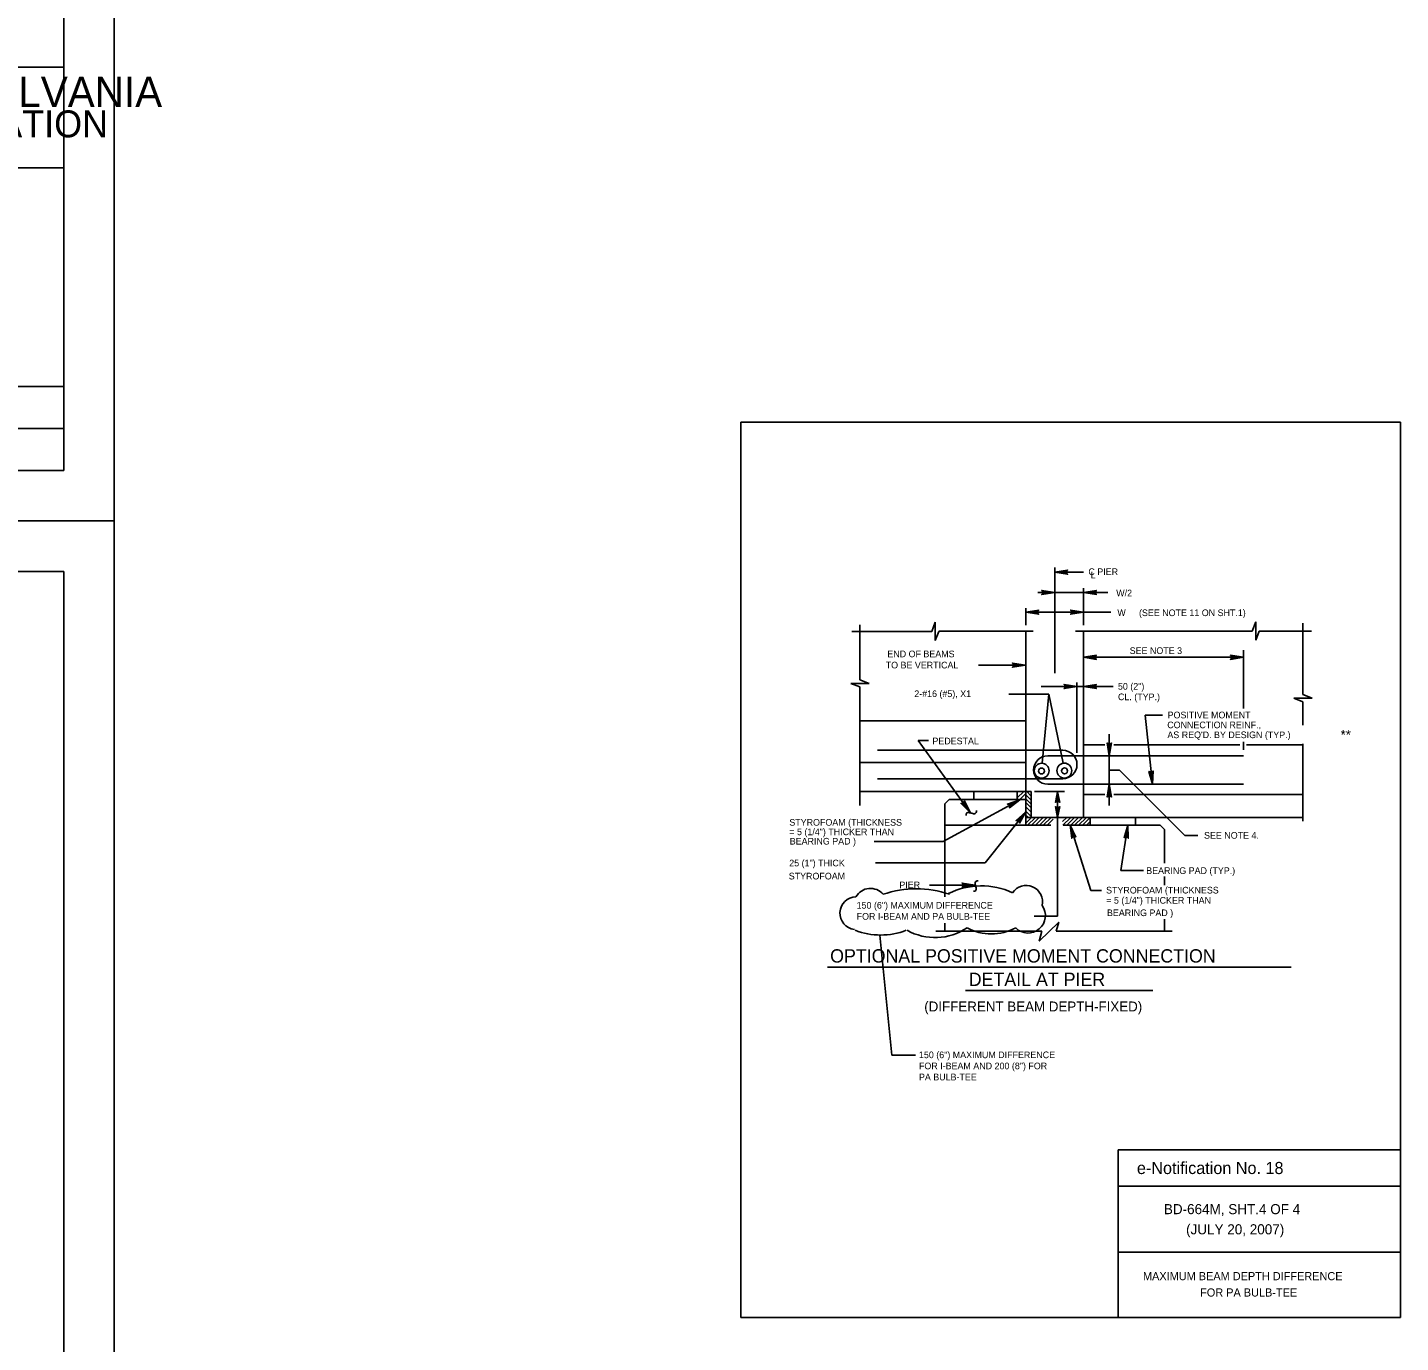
# Model space of a CAD drawing. Extents: x 639980 to 641204, y 298038 to 300414.
# Drawn here: x 640795.5 to 641204.2, y 298387.4 to 298778.6 of the extents above; entities that cross this region are included whole.
import ezdxf

# ---------------------------------------------------------------- set-up
doc = ezdxf.new("R2010")
doc.units = 0
for name, color, linetype in [('1', 7, 'Continuous'), ('2', 7, 'Continuous'), ('3', 7, 'Continuous'), ('PLT-BNDY', 7, 'Continuous')]:
    doc.layers.add(name, color=color, linetype=linetype)

msp = doc.modelspace()

# ---------------------------------------------------------------- linework, layer by layer
at = {"layer": '1'}
for p, q in [((641101.22, 298586.45), (641101.22, 298617.92)), ((641092.63, 298541.26), (641092.63, 298598.95)), ((641109.81, 298543.59), (641109.81, 298598.95)), ((641097.52, 298559.68), (641099.5, 298580.25)), ((641090.09, 298548.96), (641090.09, 298551.29)), ((641111.74, 298541.26), (641111.74, 298543.59)), ((641096.59, 298506.76), (641102.42, 298512.39)), ((641096.59, 298506.76), (641097.37, 298509.71)), ((641102.42, 298512.39), (641101.66, 298509.71))]:
    msp.add_line(p, q, dxfattribs=at)
for points in [[(641077.9, 298545.61), (641077.85, 298545.08), (641077.58, 298544.79), (641077.08, 298544.68), (641076.6, 298544.82), (641076.1, 298544.92), (641075.6, 298545.01), (641075.1, 298544.95), (641074.88, 298544.58), (641074.88, 298544.17)], [(641078.45, 298524.69), (641077.92, 298524.65), (641077.63, 298524.38), (641077.52, 298523.87), (641077.66, 298523.4), (641077.76, 298522.9), (641077.85, 298522.39), (641077.79, 298521.89), (641077.42, 298521.68), (641077.01, 298521.68)]]:
    msp.add_spline(points, degree=3, dxfattribs=at)
at = {"layer": '2'}
for p, q in [((640806.31, 299210.78), (640806.31, 298646.78)), ((640806.31, 298766.78), (640606.31, 298766.78)), ((640806.31, 298646.78), (640806.31, 298766.78)), ((640806.31, 298736.78), (640606.31, 298736.78)), ((640806.31, 298736.78), (640606.31, 298736.78)), ((640806.31, 298671.78), (640606.31, 298671.78)), ((640806.31, 298671.78), (640606.31, 298671.78)), ((641204.16, 298661.17), (641007.76, 298661.17)), ((641007.76, 298394.77), (641007.76, 298661.17)), ((641204.16, 298394.77), (641204.16, 298661.17)), ((640756.31, 298659.28), (640806.31, 298659.28)), ((640806.31, 298646.78), (640020.31, 298646.78)), ((640606.31, 298646.78), (640806.31, 298646.78)), ((640020.31, 298616.78), (640806.31, 298616.78)), ((640806.31, 298616.78), (640806.31, 298052.78)), ((641109.81, 298616.55), (641101.22, 298616.55)), ((641109.81, 298600.73), (641109.81, 298611.81)), ((641101.22, 298610.5), (641096.2, 298610.5)), ((641109.81, 298610.5), (641101.22, 298610.5)), ((641117.01, 298610.5), (641109.81, 298610.5)), ((641092.63, 298600.73), (641092.63, 298605.87)), ((641109.81, 298604.63), (641092.63, 298604.63)), ((641117.95, 298604.63), (641109.81, 298604.63)), ((641064.61, 298598.91), (641040.88, 298598.91)), ((641043.21, 298584.52), (641043.21, 298600.89)), ((641064.61, 298598.91), (641065.69, 298601.67)), ((641065.69, 298601.67), (641065.69, 298596.23)), ((641065.69, 298596.23), (641066.73, 298598.91)), ((641094.8, 298598.95), (641066.73, 298598.95)), ((641159.97, 298598.95), (641107.42, 298598.95)), ((641159.97, 298598.99), (641161.04, 298601.75)), ((641161.04, 298601.75), (641161.04, 298596.31)), ((641161.04, 298596.31), (641162.09, 298598.99)), ((641177.62, 298598.99), (641162.09, 298598.99)), ((641175.12, 298580.11), (641175.12, 298601.38)), ((641157.37, 298591.22), (641109.81, 298591.22)), ((641157.37, 298576.03), (641157.37, 298593.29)), ((641092.5, 298588.86), (641078.53, 298588.86)), ((641045.97, 298583.45), (641040.53, 298583.45)), ((641040.53, 298583.45), (641043.21, 298582.4)), ((641043.21, 298584.52), (641045.97, 298583.45)), ((641043.24, 298547.12), (641043.24, 298582.4)), ((641109.81, 298582.51), (641097.18, 298582.51)), ((641107.86, 298562.75), (641107.86, 298583.69)), ((641118.61, 298582.51), (641109.81, 298582.51)), ((641099.5, 298580.25), (641087.55, 298580.25)), ((641099.5, 298580.25), (641103.7, 298559.69)), ((641177.84, 298579.03), (641172.4, 298579.03)), ((641172.4, 298579.03), (641175.08, 298577.99)), ((641175.08, 298580.11), (641177.84, 298579.03)), ((641175.12, 298571.03), (641175.12, 298577.99)), ((641043.24, 298572.3), (641092.63, 298572.3)), ((641128.12, 298573.98), (641133.29, 298573.98)), ((641130.31, 298553.52), (641128.12, 298573.98)), ((641076.04, 298545.04), (641060.54, 298566.45)), ((641063.66, 298566.45), (641060.54, 298566.45)), ((641157.37, 298563.7), (641157.37, 298566.08)), ((641103.63, 298563.56), (641048.51, 298563.56)), ((641109.81, 298565.15), (641116.13, 298565.15)), ((641118.83, 298565.15), (641156.33, 298565.15)), ((641158.35, 298565.15), (641175.12, 298565.15)), ((641175.12, 298542.51), (641175.12, 298565.52)), ((641043.24, 298559.88), (641092.63, 298559.88)), ((641099.18, 298561.91), (641157.37, 298561.91)), ((641118.61, 298561.91), (641111.97, 298561.91)), ((641103.63, 298555.1), (641048.51, 298555.1)), ((641117.48, 298557.68), (641120.49, 298557.68)), ((641139.93, 298538.25), (641120.49, 298557.68)), ((641043.24, 298551.29), (641094.26, 298551.29)), ((641077.16, 298548.96), (641077.16, 298551.29)), ((641090.09, 298549.36), (641092.04, 298551.31)), ((641090.84, 298548.94), (641092.63, 298550.73)), ((641092.63, 298550.32), (641094.26, 298548.69)), ((641092.92, 298551.29), (641094.26, 298549.95)), ((641094.26, 298543.61), (641094.26, 298551.29)), ((641104.12, 298551.29), (641095.23, 298551.29)), ((641099.18, 298553.45), (641157.37, 298553.45)), ((641102.1, 298543.59), (641102.1, 298551.23)), ((641110.03, 298550.39), (641116.17, 298550.39)), ((641118.79, 298550.39), (641175.12, 298550.39)), ((641068.01, 298536.41), (641088.46, 298547.51)), ((641068.56, 298547.67), (641069.83, 298548.94)), ((641068.56, 298519.91), (641068.56, 298547.67)), ((641069.83, 298548.94), (641092.63, 298548.94)), ((641092.63, 298549.14), (641094.26, 298547.5)), ((641092.63, 298548.05), (641094.26, 298546.42)), ((641092.63, 298546.76), (641094.26, 298545.13)), ((641092.63, 298545.26), (641080.52, 298530.05)), ((641092.63, 298545.48), (641094.26, 298543.85)), ((641092.63, 298544.2), (641093.22, 298543.61)), ((641092.63, 298543.59), (641175.12, 298543.59)), ((641092.63, 298541.9), (641094.31, 298543.59)), ((641093.15, 298541.26), (641095.48, 298543.59)), ((641094.32, 298541.26), (641096.64, 298543.59)), ((641095.48, 298541.26), (641097.81, 298543.59)), ((641096.65, 298541.26), (641098.98, 298543.59)), ((641097.82, 298541.26), (641100.14, 298543.59)), ((641098.98, 298541.26), (641100.8, 298543.08)), ((641102.1, 298514.24), (641102.1, 298543.59)), ((641103.55, 298542.33), (641104.81, 298543.59)), ((641103.65, 298541.26), (641105.98, 298543.59)), ((641104.82, 298541.26), (641107.14, 298543.59)), ((641105.99, 298541.26), (641108.31, 298543.59)), ((641107.15, 298541.26), (641109.48, 298543.59)), ((641108.32, 298541.26), (641110.64, 298543.59)), ((641109.49, 298541.26), (641111.74, 298543.52)), ((641110.65, 298541.26), (641111.74, 298542.35)), ((641125.28, 298541.26), (641125.28, 298543.59)), ((641068.56, 298541.26), (641100.06, 298541.26)), ((641103.79, 298541.26), (641132.59, 298541.26)), ((641112.02, 298521.86), (641105.87, 298541.26)), ((641120.92, 298527.79), (641122.97, 298541.26)), ((641133.88, 298539.97), (641132.59, 298541.26)), ((641133.88, 298529.96), (641133.88, 298539.97)), ((641143.8, 298538.25), (641139.93, 298538.25)), ((641068.01, 298536.41), (641047.5, 298536.41)), ((641080.52, 298530.05), (641047.87, 298530.05)), ((641127.64, 298527.79), (641120.92, 298527.79)), ((641133.88, 298523.41), (641133.88, 298526.02)), ((641063.93, 298523.46), (641077.5, 298523.46)), ((641115.16, 298521.86), (641112.02, 298521.86)), ((641102.1, 298514.24), (641095.12, 298514.24)), ((641133.88, 298509.71), (641133.88, 298513.36)), ((641097.37, 298509.71), (641065.88, 298509.71)), ((641068.56, 298509.71), (641068.56, 298512.11)), ((641136.2, 298509.71), (641101.66, 298509.71)), ((641052.79, 298472.85), (641049.2, 298508.58)), ((641033.58, 298499.06), (641171.64, 298499.06)), ((641074.69, 298492.07), (641130.44, 298492.07)), ((641059.77, 298472.85), (641052.79, 298472.85)), ((641204.16, 298394.77), (641204.16, 298454.77)), ((641204.16, 298444.67), (641120.11, 298444.67)), ((641120.11, 298444.67), (641120.11, 298394.77)), ((641204.16, 298433.84), (641120.11, 298433.84)), ((641204.16, 298414.27), (641120.11, 298414.27)), ((641204.16, 298394.77), (641007.76, 298394.77))]:
    msp.add_line(p, q, dxfattribs=at)
for points in [[(641104.87, 298616.09), (641104.74, 298616.35), (641101.22, 298616.55), (641104.87, 298616.09), (641105.06, 298615.93), (641101.22, 298616.55), (641104.73, 298616.72), (641104.86, 298616.98), (641101.22, 298616.55), (641105.06, 298617.16), (641104.86, 298616.98)], [(641097.57, 298610.96), (641097.7, 298610.7), (641101.22, 298610.5), (641097.57, 298610.96), (641097.38, 298611.12), (641101.22, 298610.5), (641097.7, 298610.33), (641097.58, 298610.07), (641101.22, 298610.5), (641097.38, 298609.89), (641097.58, 298610.07)], [(641113.47, 298610.05), (641113.33, 298610.31), (641109.81, 298610.5), (641113.47, 298610.05), (641113.65, 298609.89), (641109.81, 298610.5), (641113.33, 298610.68), (641113.46, 298610.94), (641109.81, 298610.5), (641113.65, 298611.11), (641113.46, 298610.94)], [(641096.28, 298604.17), (641096.14, 298604.44), (641092.63, 298604.63), (641096.28, 298604.17), (641096.47, 298604.01), (641092.63, 298604.63), (641096.14, 298604.8), (641096.27, 298605.07), (641092.63, 298604.63), (641096.47, 298605.24), (641096.27, 298605.07)], [(641096.28, 298604.17), (641096.14, 298604.44), (641092.63, 298604.63), (641096.28, 298604.17), (641096.47, 298604.01), (641092.63, 298604.63), (641096.14, 298604.8), (641096.27, 298605.07), (641092.63, 298604.63), (641096.47, 298605.24), (641096.27, 298605.07)], [(641106.16, 298605.09), (641106.29, 298604.82), (641109.81, 298604.63), (641106.16, 298605.09), (641105.97, 298605.25), (641109.81, 298604.63), (641106.3, 298604.46), (641106.17, 298604.19), (641109.81, 298604.63), (641105.97, 298604.02), (641106.17, 298604.19)], [(641113.47, 298590.76), (641113.33, 298591.02), (641109.81, 298591.22), (641113.47, 298590.76), (641113.65, 298590.6), (641109.81, 298591.22), (641113.33, 298591.39), (641113.46, 298591.65), (641109.81, 298591.22), (641113.65, 298591.83), (641113.46, 298591.65)], [(641153.72, 298591.68), (641153.86, 298591.41), (641157.37, 298591.22), (641153.72, 298591.68), (641153.53, 298591.84), (641157.37, 298591.22), (641153.86, 298591.05), (641153.73, 298590.78), (641157.37, 298591.22), (641153.53, 298590.61), (641153.73, 298590.78)], [(641088.85, 298589.32), (641088.98, 298589.06), (641092.5, 298588.86), (641088.85, 298589.32), (641088.66, 298589.48), (641092.5, 298588.86), (641088.98, 298588.69), (641088.86, 298588.43), (641092.5, 298588.86), (641088.66, 298588.25), (641088.86, 298588.43)], [(641104.2, 298582.97), (641104.34, 298582.7), (641107.86, 298582.51), (641104.2, 298582.97), (641104.02, 298583.13), (641107.86, 298582.51), (641104.34, 298582.34), (641104.21, 298582.07), (641107.86, 298582.51), (641104.02, 298581.9), (641104.21, 298582.07)], [(641113.47, 298582.05), (641113.33, 298582.32), (641109.81, 298582.51), (641113.47, 298582.05), (641113.65, 298581.89), (641109.81, 298582.51), (641113.33, 298582.68), (641113.46, 298582.95), (641109.81, 298582.51), (641113.65, 298583.12), (641113.46, 298582.95)], [(641117.02, 298565.56), (641117.29, 298565.43), (641117.48, 298561.91), (641117.02, 298565.56), (641116.86, 298565.75), (641117.48, 298561.91), (641117.65, 298565.42), (641117.92, 298565.55), (641117.48, 298561.91), (641118.09, 298565.75), (641117.92, 298565.55)], [(641130.37, 298557.2), (641130.13, 298557.04), (641130.31, 298553.52), (641130.37, 298557.2), (641130.51, 298557.41), (641130.31, 298553.52), (641129.76, 298557), (641129.49, 298557.1), (641130.31, 298553.52), (641129.29, 298557.28), (641129.49, 298557.1)], [(641102.56, 298548.19), (641102.29, 298548.3), (641102.1, 298551.23), (641102.56, 298548.19), (641102.72, 298548.03), (641102.1, 298551.23), (641101.93, 298548.3), (641101.66, 298548.19), (641102.1, 298551.23), (641101.49, 298548.03), (641101.66, 298548.19)], [(641117.02, 298549.8), (641117.29, 298549.93), (641117.48, 298553.45), (641117.02, 298549.8), (641116.86, 298549.61), (641117.48, 298553.45), (641117.65, 298549.94), (641117.92, 298549.81), (641117.48, 298553.45), (641118.09, 298549.61), (641117.92, 298549.81)], [(641074.3, 298548.29), (641074.17, 298548.02), (641076.04, 298545.04), (641074.3, 298548.29), (641074.33, 298548.53), (641076.04, 298545.04), (641073.87, 298547.81), (641073.58, 298547.76), (641076.04, 298545.04), (641073.32, 298547.82), (641073.58, 298547.76)], [(641087.41, 298547.51), (641087.65, 298547.34), (641090.87, 298548.79), (641087.41, 298547.51), (641087.17, 298547.57), (641090.87, 298548.79), (641087.83, 298547.01), (641087.83, 298546.72), (641090.87, 298548.79), (641087.74, 298546.47), (641087.83, 298546.72)], [(641102.56, 298546.63), (641102.29, 298546.52), (641102.1, 298543.59), (641102.56, 298546.63), (641102.72, 298546.79), (641102.1, 298543.59), (641101.93, 298546.52), (641101.66, 298546.62), (641102.1, 298543.59), (641101.49, 298546.79), (641101.66, 298546.62)], [(641089.99, 298542.69), (641090.28, 298542.63), (641092.63, 298545.26), (641089.99, 298542.69), (641089.75, 298542.64), (641092.63, 298545.26), (641090.57, 298542.4), (641090.7, 298542.14), (641092.63, 298545.26), (641090.71, 298541.88), (641090.7, 298542.14)], [(641106.42, 298537.62), (641106.64, 298537.83), (641105.87, 298541.26), (641106.42, 298537.62), (641106.32, 298537.4), (641105.87, 298541.26), (641106.99, 298537.93), (641107.28, 298537.88), (641105.87, 298541.26), (641107.5, 298537.73), (641107.28, 298537.88)], [(641122.08, 298537.69), (641122.36, 298537.79), (641122.97, 298541.26), (641122.08, 298537.69), (641121.9, 298537.52), (641122.97, 298541.26), (641122.72, 298537.75), (641122.97, 298537.59), (641122.97, 298541.26), (641123.12, 298537.38), (641122.97, 298537.59)], [(641073.84, 298523), (641073.98, 298523.26), (641077.5, 298523.46), (641073.84, 298523), (641073.65, 298522.84), (641077.5, 298523.46), (641073.98, 298523.63), (641073.85, 298523.89), (641077.5, 298523.46), (641073.65, 298524.07), (641073.85, 298523.89)]]:
    msp.add_lwpolyline(points, dxfattribs=at)
for centre, radius in [((641097.35, 298557.47), 2.22), ((641097.3, 298557.39), 0.89), ((641104.09, 298557.51), 2.22), ((641104.16, 298557.43), 0.89)]:
    msp.add_circle(centre, radius, dxfattribs=at)
for centre, radius, start, end in [((641103.63, 298559.33), 4.23, 270, 90), ((641099.18, 298557.68), 4.23, 90, 270), ((641046.36, 298517.49), 4.97, 40.3421, 149.7428), ((641060.02, 298492.32), 30.05, 70.8276, 109.1724), ((641079.42, 298501.06), 22.16, 65.286, 116.1463), ((641092.72, 298518.46), 4.88, 347.2344, 145.9951), ((641042.19, 298515.1), 4.89, 91.4818, 262.9328), ((641093.3, 298514.35), 5.16, 224.7417, 35.8865), ((641049.44, 298529.59), 21.01, 248.7607, 291.2393), ((641065.62, 298524.95), 17.11, 240.8463, 303.7349), ((641082.38, 298524.46), 15.54, 242.1744, 297.8256)]:
    msp.add_arc(centre, radius, start, end, dxfattribs=at)
at = {"layer": '3'}
msp.add_line((641117.48, 298547.1), (641117.48, 298568.3), dxfattribs=at)
at = {"layer": 'PLT-BNDY'}
for points in [[(639980.31, 299225.78), (640821.31, 299225.78), (640821.31, 298631.78), (639980.31, 298631.78)], [(639980.31, 298631.78), (640821.31, 298631.78), (640821.31, 298037.78), (639980.31, 298037.78)]]:
    msp.add_lwpolyline(points, close=True, dxfattribs=at)

# ---------------------------------------------------------------- texts
at = {"layer": '2'}
for s, height, p in [('COMMONWEALTH OF PENNSYLVANIA', 9, (640613.56, 298754.91)), ('DEPARTMENT OF TRANSPORTATION', 8.0002, (640626.31, 298745.91)), ('(SEE NOTE 11 ON SHT.1)', 1.98, (641126.31, 298603.47)), ('SEE NOTE 3', 1.98, (641123.54, 298592.21)), ('SEE NOTE 4.', 1.98, (641145.67, 298537.25)), ('OPTIONAL POSITIVE MOMENT CONNECTION', 3.96, (641034.39, 298500.41)), ('DETAIL AT PIER', 3.96, (641075.64, 298493.43)), ('(DIFFERENT BEAM DEPTH-FIXED)', 2.97, (641062.4, 298485.85)), ('e-Notification No. 18', 3.6, (641125.7, 298437.49)), ('BD-664M, SHT.4 OF 4', 3, (641133.72, 298425.55)), ('(JULY 20, 2007)', 3, (641140.33, 298419.55)), ('MAXIMUM BEAM DEPTH DIFFERENCE', 2.43, (641127.5, 298405.9)), ('FOR PA BULB-TEE', 2.43, (641144.51, 298401.04))]:
    msp.add_text(s, height=height, dxfattribs=at).set_placement(p)
at = {"layer": '3'}
for s, height, p in [('C PIER', 1.979, (641111.26, 298615.69)), ('L', 1.98, (641111.94, 298614.73)), ('W/2', 1.978, (641119.54, 298609.34)), ('W', 1.98, (641119.87, 298603.53)), ('END OF BEAMS', 1.9793, (641051.42, 298591.23)), ('TO BE VERTICAL', 1.9793, (641050.93, 298587.91)), ('50 (2")', 1.978, (641120.05, 298581.58)), ('2-#16 (#5), X1', 1.9779, (641059.43, 298579.38)), ('CL. (TYP.)', 1.978, (641120.06, 298578.46)), ('POSITIVE MOMENT', 1.9779, (641134.83, 298573.06)), ('CONNECTION REINF.,', 1.9779, (641134.72, 298570.11)), ('PEDESTAL', 1.979, (641064.83, 298565.32)), ("AS REQ'D. BY DESIGN (TYP.)", 1.9779, (641134.77, 298567.16)), ('**', 2.967, (641186.31, 298566.67)), ('STYROFOAM (THICKNESS ', 1.9793, (641022.24, 298541.12)), ('= 5 (1/4") THICKER THAN', 1.9793, (641022.24, 298538.3)), ('BEARING PAD )', 1.9793, (641022.37, 298535.51)), ('25 (1") THICK', 1.9793, (641022.21, 298529.02)), ('STYROFOAM', 1.979, (641022.07, 298525.13)), ('BEARING PAD (TYP.)', 1.9793, (641128.46, 298526.76)), ('PIER', 1.979, (641054.99, 298522.52)), ('STYROFOAM (THICKNESS ', 1.9793, (641116.52, 298520.95)), ('150 (6") MAXIMUM DIFFERENCE', 1.9799, (641042.27, 298516.45)), ('= 5 (1/4") THICKER THAN', 1.9793, (641116.58, 298517.92)), ('FOR I-BEAM AND PA BULB-TEE', 1.9799, (641042.27, 298513.15)), ('BEARING PAD )', 1.9793, (641116.78, 298514.22)), ('150 (6") MAXIMUM DIFFERENCE', 1.9799, (641060.82, 298471.96)), ('FOR I-BEAM AND 200 (8") FOR', 1.9799, (641060.82, 298468.66)), ('PA BULB-TEE', 1.9799, (641060.82, 298465.36))]:
    msp.add_text(s, height=height, dxfattribs=at).set_placement(p)

doc.saveas('drawing.dxf')
